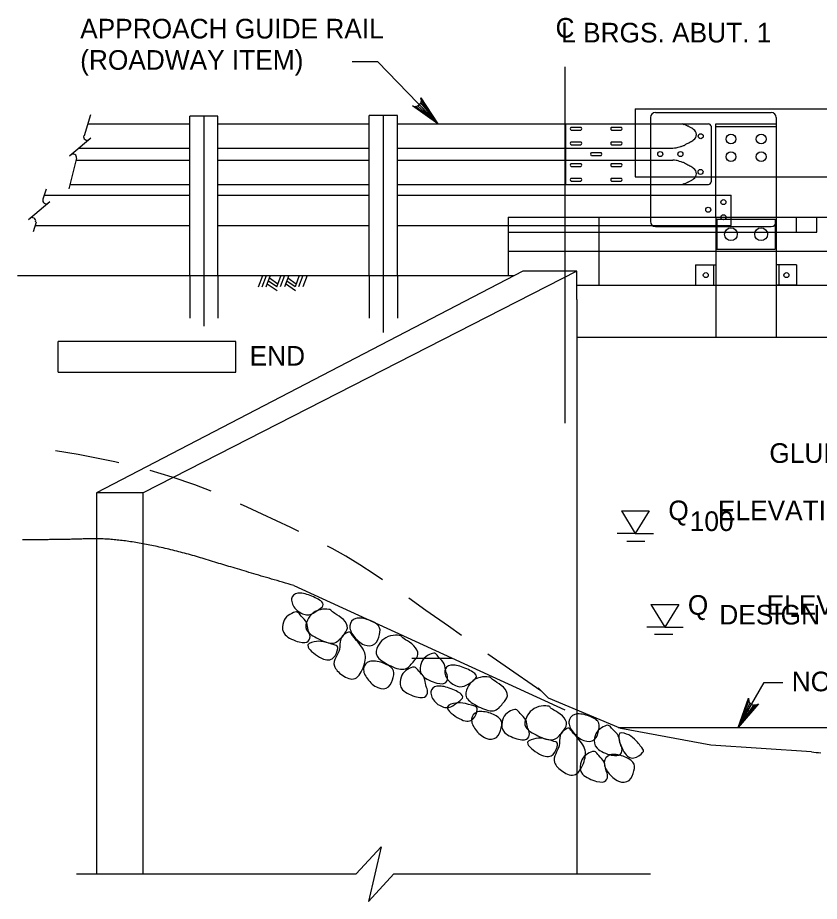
# Model space of a CAD drawing. Extents: x 638268 to 640277, y 295465 to 298435.
# Drawn here: x 638482.9 to 638605.4, y 297404.8 to 297539.8 of the extents above; entities that cross this region are included whole.
import ezdxf

# ---------------------------------------------------------------- set-up
doc = ezdxf.new("R2010")
doc.units = 0
for name, color, linetype in [('2', 7, 'Continuous'), ('3', 7, 'Continuous'), ('4', 7, 'Continuous'), ('52', 7, 'Continuous'), ('8', 7, 'Continuous'), ('Level 25', 7, 'Continuous')]:
    doc.layers.add(name, color=color, linetype=linetype)

msp = doc.modelspace()

# ---------------------------------------------------------------- linework, layer by layer
at = {"layer": '2'}
for p, q in [((638577.23, 297525.9), (638577.23, 297523.59)), ((638577.23, 297525.9), (638750.23, 297525.9)), ((638493.6, 297523.6), (638509.18, 297523.6)), ((638513.5, 297523.6), (638536.57, 297523.6)), ((638540.9, 297523.6), (638566.58, 297523.6)), ((638566.58, 297523.6), (638566.58, 297514.36)), ((638566.64, 297523.6), (638577.23, 297523.6)), ((638577.23, 297523.6), (638588.44, 297523.6)), ((638577.23, 297523.59), (638577.23, 297515.51)), ((638589.55, 297523.59), (638598.78, 297523.59)), ((638589.55, 297509.34), (638589.55, 297523.59)), ((638598.78, 297523.59), (638598.78, 297509.34)), ((638567.45, 297523.09), (638568.92, 297523.09)), ((638567.45, 297522.63), (638568.92, 297522.63)), ((638573.62, 297523.09), (638575.1, 297523.09)), ((638573.62, 297522.63), (638575.1, 297522.63)), ((638588.81, 297523.23), (638588.81, 297514.73)), ((638589.55, 297523.21), (638598.78, 297523.21)), ((638567.45, 297520.88), (638568.92, 297520.88)), ((638573.62, 297520.88), (638575.1, 297520.88)), ((638492.25, 297519.91), (638509.18, 297519.91)), ((638513.5, 297519.91), (638536.57, 297519.91)), ((638540.9, 297519.91), (638577.23, 297519.91)), ((638567.45, 297520.41), (638568.92, 297520.41)), ((638573.62, 297520.41), (638575.1, 297520.41)), ((638577.23, 297519.91), (638582.98, 297519.91)), ((638570.53, 297519.21), (638572.01, 297519.21)), ((638570.53, 297518.75), (638572.01, 297518.75)), ((638491.81, 297518.06), (638509.18, 297518.06)), ((638513.5, 297518.06), (638536.57, 297518.06)), ((638540.9, 297518.06), (638577.23, 297518.06)), ((638567.45, 297517.55), (638568.92, 297517.55)), ((638567.45, 297517.09), (638568.92, 297517.09)), ((638573.62, 297517.55), (638575.1, 297517.55)), ((638573.62, 297517.09), (638575.1, 297517.09)), ((638577.23, 297518.06), (638582.98, 297518.06)), ((638577.23, 297515.51), (638579.54, 297515.51)), ((638579.54, 297515.51), (638589.55, 297515.51)), ((638589.55, 297515.51), (638598.78, 297515.51)), ((638598.78, 297515.51), (638635.84, 297515.51)), ((638490.88, 297514.36), (638509.18, 297514.36)), ((638513.5, 297514.36), (638536.57, 297514.36)), ((638540.9, 297514.36), (638579.54, 297514.36)), ((638567.45, 297515.33), (638568.92, 297515.33)), ((638567.45, 297514.87), (638568.92, 297514.87)), ((638573.62, 297515.33), (638575.1, 297515.33)), ((638573.62, 297514.87), (638575.1, 297514.87)), ((638579.54, 297514.36), (638588.44, 297514.36)), ((638486.95, 297512.7), (638509.18, 297512.7)), ((638513.5, 297512.7), (638536.57, 297512.7)), ((638540.9, 297512.7), (638579.54, 297512.7)), ((638579.54, 297512.7), (638591.89, 297512.7)), ((638591.89, 297508.08), (638591.89, 297512.7)), ((638557.8, 297509.34), (638589.55, 297509.34)), ((638557.8, 297509.34), (638557.8, 297500.4)), ((638571.65, 297509.34), (638571.65, 297498.96)), ((638579.54, 297509.34), (638579.54, 297508.68)), ((638589.55, 297509.34), (638598.78, 297509.34)), ((638589.55, 297509.34), (638589.55, 297491.02)), ((638589.71, 297509.06), (638589.71, 297504.45)), ((638589.71, 297509.06), (638598.59, 297509.06)), ((638598.59, 297509.06), (638598.59, 297504.45)), ((638598.78, 297509.34), (638635.84, 297509.34)), ((638598.78, 297509.34), (638598.78, 297491.02)), ((638601.86, 297507.04), (638601.86, 297509.34)), ((638604.95, 297507.04), (638604.95, 297509.34)), ((638485.55, 297508.08), (638509.18, 297508.08)), ((638513.5, 297508.08), (638536.57, 297508.08)), ((638540.9, 297508.08), (638557.8, 297508.08)), ((638557.8, 297508.08), (638591.89, 297508.08)), ((638557.8, 297507.04), (638604.95, 297507.04)), ((638557.8, 297504.15), (638589.55, 297504.15)), ((638589.55, 297504.15), (638598.78, 297504.15)), ((638589.71, 297504.45), (638598.59, 297504.45)), ((638598.78, 297504.15), (638614.94, 297504.15)), ((638586.45, 297502.05), (638589.55, 297502.05)), ((638586.45, 297502.05), (638586.45, 297498.96)), ((638589.18, 297502.05), (638589.18, 297498.96)), ((638589.55, 297502.05), (638589.55, 297498.96)), ((638598.78, 297502.05), (638598.78, 297498.96)), ((638601.87, 297502.05), (638598.78, 297502.05)), ((638599.15, 297502.05), (638599.15, 297498.96)), ((638601.87, 297502.05), (638601.87, 297498.96)), ((638586.45, 297498.96), (638589.55, 297498.96)), ((638589.55, 297498.96), (638598.78, 297498.96)), ((638601.87, 297498.96), (638598.78, 297498.96)), ((638598.78, 297498.96), (638635.84, 297498.96))]:
    msp.add_line(p, q, dxfattribs=at)
for centre, radius in [((638587.23, 297521.72), 0.385), ((638591.85, 297521.28), 0.748), ((638596.47, 297521.28), 0.748), ((638581.05, 297518.99), 0.385), ((638584.13, 297518.99), 0.385), ((638591.85, 297518.59), 0.748), ((638596.47, 297518.59), 0.748), ((638587.21, 297516.27), 0.385), ((638590.7, 297511.65), 0.385), ((638588.39, 297510.49), 0.385), ((638590.7, 297509.34), 0.385), ((638591.85, 297506.75), 0.978), ((638596.46, 297506.75), 0.978), ((638588.01, 297500.5), 0.385), ((638600.32, 297500.5), 0.385)]:
    msp.add_circle(centre, radius, dxfattribs=at)
for centre, radius, start, end in [((638581.4, 297513.88), 10.17, 71.5066, 72.9766), ((638588.44, 297523.23), 0.369, 0, 90), ((638567.58, 297522.86), 0.269, 120.8559, 239.1441), ((638568.79, 297522.86), 0.269, 300.8559, 59.1441), ((638573.76, 297522.86), 0.269, 120.8559, 239.1441), ((638574.96, 297522.86), 0.269, 300.8559, 59.1441), ((638584.03, 297521.73), 1.88, 68.0907, 71.5066), ((638560.58, 297463.43), 64.73, 67.6851, 68.0907), ((638582.91, 297517.82), 5.93, 66.3453, 67.6851), ((638584.32, 297521.04), 2.42, 63.4251, 66.3453), ((638571.17, 297494.76), 31.8, 62.6202, 63.4251), ((638585.36, 297522.15), 0.955, 54.6771, 62.6202), ((638583.36, 297519.33), 4.42, 50.9849, 54.6771), ((638585.67, 297521.97), 0.916, 301.3851, 59.6468), ((638567.58, 297520.65), 0.269, 120.8559, 239.1441), ((638568.79, 297520.65), 0.269, 300.8559, 59.1441), ((638573.76, 297520.65), 0.269, 120.8559, 239.1441), ((638574.96, 297520.65), 0.269, 300.8559, 59.1441), ((638398.16, 297866.04), 392.83, 298.4725, 298.525), ((638585.23, 297521.85), 1.09, 298.525, 306.8818), ((638582.92, 297524.93), 4.94, 306.8818, 310.7993), ((638582.75, 297524.93), 5.03, 272.6429, 278.367), ((638583.16, 297522.09), 2.16, 278.367, 287.1115), ((638556.74, 297607.92), 91.96, 287.1115, 287.3611), ((638583.24, 297523.15), 3.14, 287.3611, 288.7111), ((638578.42, 297537.38), 18.18, 288.7111, 290.2329), ((638584.49, 297520.93), 0.644, 290.2329, 298.3215), ((638574.61, 297539.25), 21.45, 298.3215, 298.7501), ((638640.28, 297419.55), 115.08, 118.565, 118.7501), ((638645.68, 297409.64), 126.36, 118.4725, 118.565), ((638570.66, 297518.98), 0.269, 120.8559, 239.1441), ((638571.87, 297518.98), 0.269, 300.8559, 59.1441), ((638567.58, 297517.32), 0.269, 120.8559, 239.1441), ((638568.79, 297517.32), 0.269, 300.8559, 59.1441), ((638573.76, 297517.32), 0.269, 120.8559, 239.1441), ((638574.96, 297517.32), 0.269, 300.8559, 59.1441), ((638582.75, 297513.03), 5.03, 81.633, 87.3571), ((638583.16, 297515.88), 2.16, 72.8885, 81.633), ((638556.74, 297430.05), 91.96, 72.6389, 72.8885), ((638583.24, 297514.82), 3.14, 71.2889, 72.6389), ((638578.42, 297500.58), 18.18, 69.7671, 71.2889), ((638584.49, 297517.03), 0.644, 61.6785, 69.7671), ((638574.61, 297498.71), 21.45, 61.2499, 61.6785), ((638640.28, 297618.42), 115.08, 241.2499, 241.435), ((638645.68, 297628.32), 126.36, 241.435, 241.5275), ((638398.16, 297171.93), 392.83, 61.475, 61.5275), ((638585.23, 297516.12), 1.09, 53.1182, 61.475), ((638582.92, 297513.04), 4.94, 49.2007, 53.1182), ((638585.67, 297516), 0.916, 300.3532, 58.6149), ((638567.58, 297515.1), 0.269, 120.8559, 239.1441), ((638568.79, 297515.1), 0.269, 300.8559, 59.1441), ((638573.76, 297515.1), 0.269, 120.8559, 239.1441), ((638574.96, 297515.1), 0.269, 300.8559, 59.1441), ((638581.4, 297524.09), 10.17, 287.0234, 288.4934), ((638584.03, 297516.23), 1.88, 288.4934, 291.9093), ((638560.58, 297574.53), 64.73, 291.9093, 292.3149), ((638582.91, 297520.14), 5.93, 292.3149, 293.6547), ((638584.32, 297516.92), 2.42, 293.6547, 296.5749), ((638571.17, 297543.2), 31.8, 296.5749, 297.3798), ((638585.36, 297515.81), 0.955, 297.3798, 305.3229), ((638583.36, 297518.64), 4.42, 305.3229, 309.0151), ((638588.44, 297514.73), 0.369, 270, 0)]:
    msp.add_arc(centre, radius, start, end, dxfattribs=at)
at = {"layer": '3'}
for p, q in [((638513.5, 297524.79), (638509.18, 297524.79)), ((638509.18, 297500.4), (638509.18, 297524.79)), ((638511.34, 297524.79), (638511.34, 297492.7)), ((638513.5, 297500.4), (638513.5, 297524.79)), ((638540.9, 297524.87), (638536.57, 297524.87)), ((638536.57, 297500.4), (638536.57, 297524.87)), ((638538.73, 297524.87), (638538.73, 297491.75)), ((638540.9, 297500.4), (638540.9, 297524.87)), ((638494.06, 297521.43), (638490.8, 297518.69)), ((638491.88, 297518.35), (638490.71, 297513.68)), ((638487.25, 297513.65), (638486.76, 297512.09)), ((638487.82, 297511.71), (638484.56, 297508.97)), ((638560.07, 297501.12), (638494.94, 297467.24)), ((638568.29, 297501.12), (638502.08, 297467.24)), ((638568.29, 297501.12), (638560.07, 297501.12)), ((638568.29, 297496.79), (638568.29, 297501.12)), ((638558.69, 297500.4), (638482.9, 297500.4)), ((638509.18, 297500.4), (638509.18, 297493.91)), ((638513.5, 297500.4), (638513.5, 297493.91)), ((638520.3, 297500.4), (638519.64, 297498.64)), ((638520.85, 297500.41), (638520.18, 297498.65)), ((638521.49, 297500.42), (638520.82, 297498.66)), ((638521.19, 297499.64), (638522.48, 297498.75)), ((638521.35, 297500.07), (638522.64, 297499.18)), ((638523.11, 297500.42), (638522.46, 297498.68)), ((638523.66, 297500.42), (638523.01, 297498.69)), ((638524.3, 297500.43), (638523.64, 297498.7)), ((638524, 297499.65), (638525.29, 297498.76)), ((638524.16, 297500.08), (638525.45, 297499.19)), ((638525.92, 297500.43), (638525.27, 297498.69)), ((638526.47, 297500.43), (638525.82, 297498.7)), ((638527.11, 297500.43), (638526.45, 297498.71)), ((638536.57, 297500.4), (638536.57, 297493.91)), ((638540.9, 297500.4), (638540.9, 297493.91)), ((638521.02, 297499.19), (638522.52, 297498.16)), ((638523.83, 297499.21), (638525.33, 297498.17)), ((638568.29, 297498.96), (638581.98, 297498.96)), ((638568.29, 297498.96), (638589.55, 297498.96)), ((638568.29, 297498.96), (638589.55, 297498.96)), ((638598.78, 297498.96), (638635.84, 297498.96)), ((638568.29, 297496.79), (638568.29, 297434.07)), ((638568.29, 297491.02), (638747.07, 297491.02)), ((638568.29, 297491.02), (638760.65, 297491.02)), ((638502.08, 297467.24), (638494.94, 297467.24)), ((638494.94, 297467.24), (638494.94, 297460.12)), ((638502.08, 297459.36), (638502.08, 297467.24)), ((638494.94, 297460.12), (638494.94, 297409.02)), ((638502.08, 297409.02), (638502.08, 297459.36)), ((638525.11, 297453.07), (638566.48, 297434.09)), ((638543.13, 297442.01), (638549.23, 297442.01)), ((638568.29, 297434.07), (638568.29, 297409.02)), ((638574.64, 297431.41), (638746.15, 297431.41)), ((638534.59, 297409.02), (638538.43, 297413.19)), ((638538.43, 297413.19), (638536.51, 297404.84)), ((638491.9, 297409.02), (638534.59, 297409.02)), ((638536.51, 297404.84), (638540.35, 297409.02)), ((638540.35, 297409.02), (638579.55, 297409.02))]:
    msp.add_line(p, q, dxfattribs=at)
for centre, radius, start, end in [((638493.5, 297521.65), 0.533, 162.1496, 312.1496), ((638491.36, 297518.47), 0.533, 130.0028, 130.0168), ((638491.36, 297518.47), 0.533, 347.4782, 130.0168), ((638487.26, 297511.93), 0.533, 162.1496, 312.1496), ((638485.12, 297508.75), 0.533, 347.4782, 130.0168), ((638485.12, 297508.74), 0.533, 130.0028, 130.0168), ((638613.42, 297498.18), 71.1, 262.5202, 263.6598)]:
    msp.add_arc(centre, radius, start, end, dxfattribs=at)
for points, degree in [([(638525.11, 297453.07), (638516.58, 297455.56), (638506.65, 297458.62), (638497.12, 297460.36), (638489.77, 297460.07), (638483.62, 297460.07)], 2), ([(638529.39, 297449.8), (638529.15, 297449.54), (638528.28, 297448.99), (638527.18, 297448.35), (638525.2, 297449.29), (638524.44, 297451.22), (638525.52, 297452.12), (638527.55, 297451.68), (638529.73, 297450.54), (638529.63, 297450.06), (638529.39, 297449.8)], 3), ([(638530.8, 297449.25), (638530.86, 297449.16), (638531.19, 297448.88), (638532.78, 297447.96), (638533.57, 297446.53), (638532.57, 297445.48), (638531.37, 297443.85), (638528.79, 297444.85), (638526.57, 297446.26), (638527.12, 297447.86), (638527.91, 297448.98), (638529.51, 297449.59), (638530.86, 297449.38), (638530.75, 297449.33), (638530.8, 297449.25)], 3), ([(638527.27, 297446.3), (638527.34, 297446), (638527.64, 297445.64), (638527.49, 297444.41), (638526.14, 297444.24), (638523.25, 297445.49), (638523.34, 297447.25), (638523.86, 297448.35), (638525.12, 297449.06), (638525.77, 297449.09), (638526.07, 297448.47), (638527.24, 297447.44), (638527.2, 297446.61), (638527.27, 297446.3)], 3), ([(638538.03, 297446.91), (638538.31, 297446.54), (638538.27, 297445.7), (638537.65, 297443.87), (638535.8, 297443.74), (638534.06, 297445.36), (638533.36, 297446.99), (638534.33, 297448.33), (638536.6, 297447.92), (638537.75, 297447.28), (638538.03, 297446.91)], 3), ([(638533.71, 297445.94), (638533.85, 297445.85), (638533.96, 297445.39), (638536.22, 297443.08), (638535.97, 297440.87), (638534.57, 297438.28), (638532.38, 297439.29), (638530.96, 297440.8), (638531.44, 297442.17), (638532.19, 297443.19), (638532.04, 297445.03), (638533.13, 297445.93), (638533.57, 297446.03), (638533.71, 297445.94)], 3), ([(638541.58, 297445.26), (638541.64, 297445.18), (638541.97, 297444.89), (638543.55, 297443.98), (638544.35, 297442.54), (638543.35, 297441.49), (638542.14, 297439.87), (638539.56, 297440.87), (638537.34, 297442.28), (638537.89, 297443.88), (638538.68, 297445), (638540.28, 297445.61), (638541.63, 297445.4), (638541.52, 297445.35), (638541.58, 297445.26)], 3), ([(638531.26, 297444.02), (638531.68, 297443.88), (638531.99, 297443.77), (638531.28, 297441.72), (638529.56, 297441.54), (638526.44, 297444.01), (638528.28, 297444.53), (638529.47, 297444.64), (638530.84, 297444.16), (638531.26, 297444.02)], 3), ([(638548.3, 297440.01), (638548.36, 297439.71), (638548.66, 297439.34), (638548.51, 297438.12), (638547.17, 297437.95), (638544.27, 297439.2), (638544.37, 297440.96), (638544.88, 297442.06), (638546.14, 297442.76), (638546.8, 297442.79), (638547.09, 297442.18), (638548.27, 297441.15), (638548.23, 297440.31), (638548.3, 297440.01)], 3), ([(638540.14, 297440.36), (638540.41, 297439.99), (638540.38, 297439.15), (638539.75, 297437.32), (638537.91, 297437.19), (638536.16, 297438.81), (638535.46, 297440.44), (638536.43, 297441.78), (638538.7, 297441.37), (638539.86, 297440.73), (638540.14, 297440.36)], 3), ([(638545.23, 297437.89), (638545.3, 297437.59), (638545.6, 297437.22), (638545.45, 297436), (638544.1, 297435.83), (638541.21, 297437.08), (638541.3, 297438.84), (638541.81, 297439.94), (638543.07, 297440.64), (638543.73, 297440.68), (638544.03, 297440.06), (638545.2, 297439.03), (638545.16, 297438.19), (638545.23, 297437.89)], 3), ([(638552.78, 297438.82), (638552.54, 297438.56), (638551.67, 297438.01), (638550.57, 297437.37), (638548.59, 297438.31), (638547.83, 297440.23), (638548.91, 297441.14), (638550.94, 297440.7), (638553.12, 297439.56), (638553.02, 297439.08), (638552.78, 297438.82)], 3), ([(638555.25, 297438.91), (638555.3, 297438.82), (638555.63, 297438.54), (638557.22, 297437.62), (638558.01, 297436.19), (638557.01, 297435.14), (638555.81, 297433.51), (638553.23, 297434.51), (638551.01, 297435.92), (638551.56, 297437.52), (638552.35, 297438.64), (638553.95, 297439.25), (638555.3, 297439.04), (638555.19, 297438.99), (638555.25, 297438.91)], 3), ([(638550.7, 297435.7), (638550.46, 297435.44), (638549.61, 297434.86), (638548.52, 297434.19), (638546.52, 297435.08), (638545.71, 297436.99), (638546.77, 297437.92), (638548.8, 297437.53), (638551.01, 297436.45), (638550.93, 297435.96), (638550.7, 297435.7)], 3), ([(638552.56, 297434.69), (638552.98, 297434.56), (638553.29, 297434.46), (638552.64, 297432.39), (638550.92, 297432.17), (638547.74, 297434.55), (638549.56, 297435.13), (638550.75, 297435.26), (638552.14, 297434.82), (638552.56, 297434.69)], 3), ([(638564.22, 297434.49), (638564.28, 297434.41), (638564.62, 297434.13), (638566.23, 297433.25), (638567.06, 297431.84), (638566.08, 297430.77), (638564.92, 297429.11), (638562.32, 297430.04), (638560.06, 297431.4), (638560.57, 297433.01), (638561.33, 297434.15), (638562.92, 297434.8), (638564.27, 297434.63), (638564.16, 297434.57), (638564.22, 297434.49)], 3), ([(638556.63, 297432.64), (638556.91, 297432.27), (638556.87, 297431.43), (638556.24, 297429.61), (638554.4, 297429.47), (638552.65, 297431.09), (638551.96, 297432.73), (638552.92, 297434.06), (638555.2, 297433.66), (638556.35, 297433.01), (638556.63, 297432.64)], 3), ([(638560.76, 297431.46), (638560.84, 297431.16), (638561.15, 297430.8), (638561.03, 297429.57), (638559.69, 297429.37), (638556.77, 297430.54), (638556.81, 297432.3), (638557.3, 297433.42), (638558.54, 297434.16), (638559.19, 297434.2), (638559.51, 297433.6), (638560.71, 297432.6), (638560.69, 297431.76), (638560.76, 297431.46)], 3), ([(638571.51, 297432.34), (638571.8, 297431.98), (638571.78, 297431.14), (638571.2, 297429.29), (638569.36, 297429.11), (638567.57, 297430.69), (638566.83, 297432.3), (638567.77, 297433.67), (638570.05, 297433.32), (638571.22, 297432.7), (638571.51, 297432.34)], 3), ([(638574.9, 297429.04), (638574.98, 297428.74), (638575.29, 297428.38), (638575.17, 297427.16), (638573.83, 297426.95), (638570.9, 297428.13), (638570.95, 297429.88), (638571.44, 297431), (638572.68, 297431.74), (638573.33, 297431.78), (638573.65, 297431.18), (638574.85, 297430.18), (638574.83, 297429.34), (638574.9, 297429.04)], 3), ([(638567.21, 297431.26), (638567.35, 297431.17), (638567.47, 297430.72), (638569.8, 297428.47), (638569.6, 297426.25), (638568.27, 297423.63), (638566.05, 297424.58), (638564.6, 297426.05), (638565.03, 297427.44), (638565.76, 297428.47), (638565.57, 297430.31), (638566.63, 297431.24), (638567.07, 297431.35), (638567.21, 297431.26)], 3), ([(638578.24, 297428.32), (638578.51, 297427.97), (638578.7, 297427.72), (638576.98, 297426.39), (638575.45, 297427.19), (638574.21, 297430.97), (638576.04, 297430.4), (638577.08, 297429.83), (638577.97, 297428.67), (638578.24, 297428.32)], 3), ([(638564.81, 297429.28), (638565.24, 297429.14), (638565.54, 297429.05), (638564.89, 297426.98), (638563.17, 297426.76), (638559.99, 297429.14), (638561.82, 297429.71), (638563, 297429.85), (638564.39, 297429.41), (638564.81, 297429.28)], 3), ([(638572.72, 297424.99), (638572.79, 297424.69), (638573.09, 297424.33), (638572.94, 297423.1), (638571.59, 297422.93), (638568.7, 297424.18), (638568.79, 297425.94), (638569.31, 297427.04), (638570.57, 297427.75), (638571.22, 297427.78), (638571.52, 297427.17), (638572.69, 297426.13), (638572.65, 297425.29), (638572.72, 297424.99)], 3), ([(638576.89, 297426.08), (638577.17, 297425.71), (638577.14, 297424.87), (638576.51, 297423.04), (638574.67, 297422.91), (638572.92, 297424.53), (638572.22, 297426.16), (638573.19, 297427.5), (638575.46, 297427.09), (638576.62, 297426.45), (638576.89, 297426.08)], 3)]:
    msp.add_open_spline(points, degree=degree, dxfattribs=at)
at = {"layer": '4'}
for p, q in [((638537.91, 297533.07), (638533.97, 297533.07)), ((638547.09, 297523.6), (638537.91, 297533.07)), ((638566.48, 297532.3), (638566.48, 297477.88)), ((638516.23, 297490.38), (638489.08, 297490.38)), ((638489.08, 297485.67), (638489.08, 297490.38)), ((638516.23, 297485.67), (638516.23, 297490.38)), ((638489.08, 297485.67), (638516.23, 297485.67)), ((638575.12, 297464.49), (638577.24, 297461.01)), ((638575.12, 297464.49), (638579.36, 297464.49)), ((638579.36, 297464.49), (638577.24, 297461.01)), ((638577.24, 297461.01), (638574.47, 297461.01)), ((638577.24, 297461.01), (638580.01, 297461.01)), ((638575.93, 297459.86), (638578.7, 297459.86)), ((638579.64, 297450.21), (638583.88, 297450.21)), ((638579.64, 297450.21), (638581.76, 297446.73)), ((638583.88, 297450.21), (638581.76, 297446.73)), ((638581.76, 297446.73), (638578.99, 297446.73)), ((638581.76, 297446.73), (638584.53, 297446.73)), ((638580.2, 297445.64), (638582.97, 297445.64)), ((638592.94, 297431.41), (638596.95, 297438.26)), ((638596.95, 297438.26), (638599.76, 297438.26))]:
    msp.add_line(p, q, dxfattribs=at)
for points in [[(638547.09, 297523.6), (638543.23, 297526.35), (638543.66, 297526.26), (638544.01, 297526.35), (638544.27, 297526.52), (638544.46, 297526.78), (638544.56, 297527.13), (638544.49, 297527.56), (638547.09, 297523.6), (638544.56, 297527.13), (638544.46, 297526.78), (638547.09, 297523.6), (638544.27, 297526.52), (638544.01, 297526.35), (638547.09, 297523.6), (638543.66, 297526.26)], [(638547.09, 297523.6), (638543.23, 297526.35), (638543.66, 297526.26), (638544.01, 297526.35), (638544.27, 297526.52), (638544.46, 297526.78), (638544.56, 297527.13), (638544.49, 297527.56), (638547.09, 297523.6), (638544.56, 297527.13), (638544.46, 297526.78), (638547.09, 297523.6), (638544.27, 297526.52), (638544.01, 297526.35), (638547.09, 297523.6), (638543.66, 297526.26)], [(638604.16, 297427.68), (638588.76, 297428.68), (638575.01, 297431.25), (638563.97, 297435.87), (638562.4, 297437.43)], [(638592.94, 297431.41), (638594.54, 297435.87), (638594.57, 297435.43), (638594.75, 297435.12), (638594.99, 297434.91), (638595.29, 297434.8), (638595.65, 297434.8), (638596.05, 297434.99), (638592.94, 297431.41), (638595.65, 297434.8), (638595.29, 297434.8), (638592.94, 297431.41), (638594.99, 297434.91), (638594.75, 297435.12), (638592.94, 297431.41), (638594.57, 297435.43)]]:
    msp.add_lwpolyline(points, dxfattribs=at)
msp.add_lwpolyline([(638594.05, 297434.25), (638594.87, 297433.76), (638593, 297431.52)], close=True, dxfattribs=at)
at = {"layer": '52'}
for p, q in [((638494.01, 297524.97), (638493.07, 297521.8)), ((638485.71, 297508.61), (638485.26, 297507.12))]:
    msp.add_line(p, q, dxfattribs=at)
at = {"layer": '8'}
for p, q in [((638492.15, 297473.12), (638488.69, 297473.68)), ((638497.74, 297472), (638492.15, 297473.12)), ((638498.35, 297471.85), (638497.74, 297472)), ((638506.51, 297469.66), (638503.12, 297470.65)), ((638509.95, 297468.48), (638506.51, 297469.66)), ((638512.44, 297467.49), (638509.95, 297468.48)), ((638517.95, 297465.04), (638516.94, 297465.51)), ((638520.25, 297463.99), (638517.95, 297465.04)), ((638522.46, 297462.96), (638520.25, 297463.99)), ((638524.62, 297461.95), (638522.46, 297462.96)), ((638525.86, 297461.35), (638524.62, 297461.95)), ((638530.92, 297458.75), (638530.25, 297459.11)), ((638533.02, 297457.56), (638530.92, 297458.75)), ((638535.16, 297456.26), (638533.02, 297457.56)), ((638537.35, 297454.84), (638535.16, 297456.26)), ((638538.63, 297453.96), (638537.35, 297454.84)), ((638545.26, 297449.29), (638542.66, 297451.14)), ((638548.69, 297446.85), (638545.26, 297449.29)), ((638550.69, 297445.44), (638548.69, 297446.85)), ((638557.36, 297440.77), (638554.71, 297442.61)), ((638562.81, 297437.02), (638557.36, 297440.77))]:
    msp.add_line(p, q, dxfattribs=at)
at = {"layer": 'Level 25'}
for p, q in [((638580.31, 297525.33), (638598.01, 297525.33)), ((638579.54, 297524.56), (638579.54, 297523.59)), ((638579.54, 297523.59), (638579.54, 297514.36)), ((638598.78, 297524.56), (638598.78, 297523.59)), ((638579.54, 297514.36), (638579.54, 297509.34)), ((638580.31, 297507.91), (638598.01, 297507.91))]:
    msp.add_line(p, q, dxfattribs=at)
for centre, start, end in [((638580.31, 297524.56), 90, 180), ((638598.01, 297524.56), 0, 90), ((638580.31, 297508.68), 180, 270), ((638598.01, 297508.68), 270, 0)]:
    msp.add_arc(centre, 0.77, start, end, dxfattribs=at)

# ---------------------------------------------------------------- texts
at = {"layer": '4'}
for s, p in [('C', (638565.06, 297536.78)), ('APPROACH GUIDE RAIL', (638492.45, 297536.65)), ('L BRGS. ABUT. 1', (638565.92, 297536.04)), ('(ROADWAY ITEM)', (638492.45, 297531.87)), ('END', (638518.33, 297486.67)), ('GLULAM STIFFENER BEAM (TYP.)', (638597.72, 297471.82)), ('Q    ELEVATION - ', (638582.29, 297463.06)), ('100', (638585.56, 297461.41)), ('Q        ELEVATION - ', (638585.27, 297448.61)), ('DESIGN', (638590.08, 297447.13)), ('NORMAL WATER ELEV. -', (638601.14, 297436.93))]:
    msp.add_text(s, height=3, dxfattribs=at).set_placement(p)

doc.saveas('drawing.dxf')
